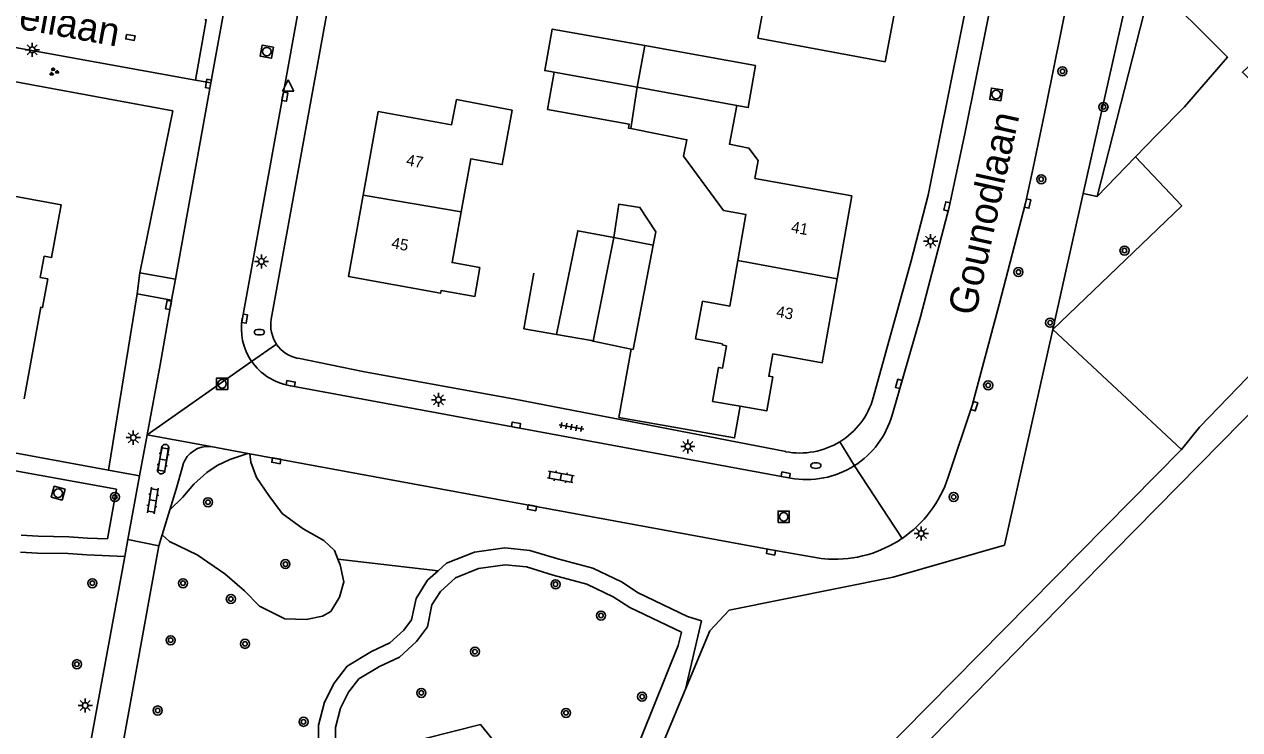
# Model space of a CAD drawing. Extents: x 132999 to 136000, y 398499 to 400501.
# Drawn here: x 133145.7 to 133253.2, y 398932.2 to 398994.6 of the extents above; entities that cross this region are included whole.
import ezdxf

# ---------------------------------------------------------------- set-up
doc = ezdxf.new("R2010")
doc.units = 0
for name, color, linetype in [('gg-afsc-erfafscheiding', 7, 'Continuous'), ('gg-afsc-hekwerk', 7, 'Continuous'), ('gg-afsc-muur', 7, 'Continuous'), ('gg-anno-huisnummerreeks BGT', 7, 'Continuous'), ('gg-anno-openbare ruimte label', 7, 'Continuous'), ('gg-bbg-bijgebouw', 7, 'Continuous'), ('gg-bbg-gedigitaliseerde bebouwing', 7, 'Continuous'), ('gg-bbg-gedigitaliseerde bijgebouw', 7, 'Continuous'), ('gg-bbg-hoofdgebouw', 7, 'Continuous'), ('gg-bbg-tussenscheiding', 7, 'Continuous'), ('gg-knt-verharding', 7, 'Continuous'), ('gt-grn-groengrens', 7, 'Continuous'), ('gt-grn-vlakafsluiter', 7, 'Continuous'), ('gt-grn-weggrens', 7, 'Continuous'), ('gt-symb-boom', 7, 'Continuous'), ('gt-symb-brandkraan', 7, 'Continuous'), ('gt-symb-groenvak', 7, 'Continuous'), ('gt-symb-klinker verharding', 7, 'Continuous'), ('gt-symb-kolk', 7, 'Continuous'), ('gt-symb-kolk center center', 7, 'Continuous'), ('gt-symb-lichtmast', 7, 'Continuous'), ('gt-symb-rioolschacht', 7, 'Continuous'), ('gt-symb-tegel verharding', 7, 'Continuous'), ('gt-symb-waterafsluiter', 7, 'Continuous')]:
    doc.layers.add(name, color=color, linetype=linetype)

# ---------------------------------------------------------------- blocks, each defined once
blk = doc.blocks.new('gt0-BOOM')
at = {"layer": 'gt-symb-boom'}
for radius in [0.4, 0.2]:
    blk.add_circle((0, 0), radius, dxfattribs=at)
blk = doc.blocks.new('gt0-LMAST')
at = {"layer": 'gt-symb-lichtmast'}
for p, q in [((-0.18, 0.17), (-0.45, 0.44)), ((-0.01, 0.25), (-0.01, 0.62)), ((0.17, 0.17), (0.44, 0.44)), ((-0.26, 0), (-0.63, 0)), ((-0.18, -0.18), (-0.45, -0.45)), ((-0.01, -0.25), (-0.01, -0.63)), ((0.44, -0.45), (0.17, -0.18)), ((0.24, 0), (0.62, 0))]:
    blk.add_line(p, q, dxfattribs=at)
blk.add_circle((-0.01, 0), 0.25, dxfattribs=at)
blk = doc.blocks.new('gt0-KOLK')
at = {"layer": 'gt-symb-kolk'}
blk.add_lwpolyline([(0, 0), (0.37, 0), (0.37, 0.4), (-0.38, 0.4), (-0.38, 0), (0, 0)], dxfattribs=at)
blk = doc.blocks.new('gt0-RS')
at = {"layer": 'gt-symb-rioolschacht'}
blk.add_lwpolyline([(-0.5, -0.5), (0.5, -0.5), (0.5, 0.5), (-0.5, 0.5)], close=True, dxfattribs=at)
blk.add_circle((0, 0), 0.375, dxfattribs=at)
blk = doc.blocks.new('gt0-BR')
at = {"layer": 'gt-symb-brandkraan'}
for centre, radius, start, end in [((-0.24, 0), 0.206, 107.5669, 252.4331), ((0.6, -2.66), 3, 106.892, 107.5669), ((0, -0.69), 0.938, 73.108, 106.892), ((-0.6, -2.66), 3, 72.4331, 73.108), ((0.24, 0), 0.206, 287.567, 72.4331), ((0.6, 2.66), 3, 252.4331, 253.108), ((0, 0.69), 0.938, 253.108, 286.8921), ((-0.6, 2.66), 3, 286.8921, 287.567)]:
    blk.add_arc(centre, radius, start, end, dxfattribs=at)
blk = doc.blocks.new('gt0-KOLKCC')
at = {"layer": 'gt-symb-kolk center center'}
blk.add_lwpolyline([(-0.38, 0.2), (0.38, 0.2), (0.38, -0.2), (-0.38, -0.2)], close=True, dxfattribs=at)
blk = doc.blocks.new('gt0-GRVAK')
at = {"layer": 'gt-symb-groenvak'}
for p, q in [((-0.11, 0.19), (-0.23, 0.24)), ((-0.18, 0.15), (0.09, 0.15)), ((-0.09, 0.21), (-0.16, 0.32)), ((-0.05, 0.21), (-0.05, 0.39)), ((0, 0.21), (0.06, 0.32)), ((0.01, 0.19), (0.13, 0.24)), ((0.26, -0.05), (0.2, 0.06)), ((0.3, -0.05), (0.3, 0.13)), ((0.35, -0.05), (0.41, 0.06)), ((-0.24, -0.23), (-0.36, -0.18)), ((-0.32, -0.26), (-0.05, -0.26)), ((-0.23, -0.21), (-0.29, -0.09)), ((-0.18, -0.2), (-0.18, -0.02)), ((-0.14, -0.21), (-0.07, -0.09)), ((-0.12, -0.23), (0, -0.18)), ((0.24, -0.07), (0.12, -0.02)), ((0.17, -0.11), (0.44, -0.11)), ((0.37, -0.07), (0.49, -0.02))]:
    blk.add_line(p, q, dxfattribs=at)
blk = doc.blocks.new('gt0-WAFSL')
at = {"layer": 'gt-symb-waterafsluiter'}
for p, q in [((-0.5, -0.33), (0, 0.67)), ((0, 0.67), (0.5, -0.33)), ((0.5, -0.33), (-0.5, -0.33))]:
    blk.add_line(p, q, dxfattribs=at)
blk = doc.blocks.new('gt0-TEG1')
at = {"layer": 'gt-symb-tegel verharding'}
for p, q in [((-1.12, 0), (1.12, 0)), ((-0.9, -0.25), (-0.9, 0.25)), ((-0.45, -0.25), (-0.45, 0.25)), ((0, -0.25), (0, 0.25)), ((0.45, -0.25), (0.45, 0.25)), ((0.9, -0.25), (0.9, 0.25))]:
    blk.add_line(p, q, dxfattribs=at)
blk = doc.blocks.new('gt0-KL1')
at = {"layer": 'gt-symb-klinker verharding'}
for p, q in [((-1.15, 0.3), (1.15, 0.3)), ((-1, -0.3), (-1, 0.3)), ((-0.5, 0.3), (-0.5, 0.45)), ((0, -0.3), (0, 0.3)), ((0.5, 0.3), (0.5, 0.45)), ((1, -0.3), (1, 0.3)), ((-1.15, -0.3), (1.15, -0.3)), ((-0.5, -0.45), (-0.5, -0.3)), ((0.5, -0.45), (0.5, -0.3))]:
    blk.add_line(p, q, dxfattribs=at)

msp = doc.modelspace()

# ---------------------------------------------------------------- linework, layer by layer
at = {"layer": 'gg-afsc-erfafscheiding'}
msp.add_line((133236.7, 398967.6), (133239.4, 398979.64), dxfattribs=at)
for points in [[(133239.4, 398979.64), (133244.97, 399004.49), (133252.84, 399038.49)], [(133208.08, 398942.76), (133222.58, 398945.69), (133232.42, 398948.53), (133236.7, 398967.6)]]:
    msp.add_lwpolyline(points, dxfattribs=at)
at = {"layer": 'gg-afsc-hekwerk'}
for points in [[(133208.08, 398942.76), (133206.38, 398940.95), (133204.22, 398935.79)], [(133204.22, 398935.79), (133193.8, 398910.84), (133190.05, 398872.02)]]:
    msp.add_lwpolyline(points, dxfattribs=at)
at = {"layer": 'gg-afsc-muur'}
msp.add_line((133189.13, 398961.44), (133175.67, 398963.87), dxfattribs=at)
for points in [[(133192.82, 398967.15), (133189.93, 398967.66), (133190.8, 398972.58)], [(133199.41, 398965.87), (133198.32, 398959.82), (133208.56, 398958), (133209.06, 398960.81)]]:
    msp.add_lwpolyline(points, dxfattribs=at)
at = {"layer": 'gg-bbg-bijgebouw'}
for p, q in [((133196.04, 398966.58), (133199.41, 398965.87)), ((133199.41, 398965.87), (133199.6, 398965.84))]:
    msp.add_line(p, q, dxfattribs=at)
for points in [[(133208.77, 398987.41), (133209.76, 398987.23), (133210.42, 398990.96)], [(133192.82, 398967.15), (133195.9, 398966.61), (133196.04, 398966.58)]]:
    msp.add_lwpolyline(points, dxfattribs=at)
at = {"layer": 'gg-bbg-gedigitaliseerde bebouwing'}
msp.add_line((133210.6, 398993.37), (133212.1, 399001.43), dxfattribs=at)
for points in [[(133184.38, 398978.01), (133185.22, 398982.69), (133188, 398982.19), (133188.87, 398986.99), (133183.96, 398987.94)], [(133199.37, 398985.37), (133204.34, 398984.39), (133204.05, 398982.94), (133207.58, 398978.13)], [(133186.03, 398973.07), (133183.57, 398973.52), (133184.38, 398978.01)], [(133208.85, 398973.71), (133209.56, 398977.78), (133207.58, 398978.13)], [(133205.71, 398970.1), (133208.14, 398969.67), (133208.85, 398973.71)]]:
    msp.add_lwpolyline(points, dxfattribs=at)
at = {"layer": 'gg-bbg-gedigitaliseerde bijgebouw'}
for p, q in [((133210.42, 398990.96), (133200.61, 398992.71)), ((133199.6, 398965.84), (133201.37, 398975.06))]:
    msp.add_line(p, q, dxfattribs=at)
for points in [[(133200.61, 398992.71), (133192.43, 398994.17), (133191.77, 398990.5), (133192.59, 398990.35)], [(133192.59, 398990.35), (133192.01, 398987.07), (133199.23, 398985.77), (133199.16, 398985.41), (133199.37, 398985.37)], [(133197.87, 398975.74), (133198.33, 398978.69), (133200.18, 398978.4), (133201.59, 398976.23), (133201.37, 398975.06)], [(133192.82, 398967.15), (133194.68, 398976.34), (133197.87, 398975.74)]]:
    msp.add_lwpolyline(points, dxfattribs=at)
at = {"layer": 'gg-bbg-hoofdgebouw'}
for p, q in [((133221.88, 398991.28), (133223.42, 398999.37)), ((133210.6, 398993.37), (133221.88, 398991.28)), ((133218.94, 398979.41), (133217.63, 398972.08))]:
    msp.add_line(p, q, dxfattribs=at)
for points in [[(133183.96, 398987.94), (133183.53, 398985.71), (133177.04, 398986.87), (133175.71, 398979.47)], [(133218.94, 398979.41), (133210.35, 398980.97), (133210.63, 398982.55), (133209.83, 398983.65), (133208.1, 398983.99), (133208.77, 398987.41)], [(133127.48, 398979.52), (133134.85, 398978.18), (133135.41, 398981.11), (133141.33, 398980.04), (133141.44, 398980.64), (133142.83, 398980.39), (133142.72, 398979.79), (133149, 398978.62), (133148.15, 398973.96), (133147.49, 398974.08), (133147.14, 398972.19), (133147.8, 398972.07), (133147.35, 398969.54), (133147.19, 398969.57), (133145.72, 398961.45)], [(133175.71, 398979.47), (133174.42, 398972.28), (133182.55, 398970.81), (133182.59, 398971.04), (133185.59, 398970.52), (133186.03, 398973.07)], [(133217.63, 398972.08), (133216.32, 398964.66), (133211.93, 398965.44)], [(133205.71, 398970.1), (133205.11, 398966.76), (133207.48, 398966.34), (133207.46, 398966.23), (133207.85, 398966.16)], [(133207.85, 398966.16), (133207.5, 398964.18), (133207.15, 398964.24), (133206.61, 398961.24), (133209.06, 398960.81)], [(133209.06, 398960.81), (133211.4, 398960.39), (133211.93, 398963.4), (133211.58, 398963.46), (133211.93, 398965.44)]]:
    msp.add_lwpolyline(points, dxfattribs=at)
at = {"layer": 'gg-bbg-tussenscheiding'}
for p, q in [((133199.95, 398989.03), (133200.61, 398992.71)), ((133199.95, 398989.03), (133192.59, 398990.35)), ((133199.95, 398989.03), (133199.37, 398985.37)), ((133199.95, 398989.03), (133208.77, 398987.41)), ((133175.71, 398979.47), (133184.38, 398978.01)), ((133196.04, 398966.58), (133197.87, 398975.74)), ((133197.87, 398975.74), (133201.37, 398975.06)), ((133208.85, 398973.71), (133217.63, 398972.08))]:
    msp.add_line(p, q, dxfattribs=at)
at = {"layer": 'gg-knt-verharding'}
for p, q in [((133185.23, 399065.78), (133167.57, 398968.5)), ((133162.23, 398989.41), (133169.19, 399028.01)), ((133165.02, 398968.61), (133175.6, 399026.92)), ((133136.32, 398994.11), (133160.87, 398989.66)), ((133160.87, 398989.66), (133162.23, 398989.41)), ((133162.23, 398989.41), (133159.1, 398972.04)), ((133155.95, 398972.61), (133159.1, 398972.04)), ((133159.1, 398972.04), (133158.76, 398970.19)), ((133155.71, 398970.74), (133158.76, 398970.19)), ((133169.94, 398965.05), (133175.67, 398963.87)), ((133169.13, 398962.64), (133213.5, 398954.45)), ((133189.13, 398961.44), (133213.08, 398956.79)), ((133156.59, 398958.27), (133155.92, 398954.64)), ((133157.91, 398957.19), (133157.53, 398955.25)), ((133158.17, 398955.12), (133158.5, 398957.08)), ((133162.23, 398957.24), (133165.51, 398956.64)), ((133165.51, 398956.64), (133165.68, 398956.61)), ((133155.92, 398954.64), (133154.89, 398949.03)), ((133157.91, 398949.42), (133158.59, 398951.65)), ((133154.89, 398949.03), (133154.61, 398947.52)), ((133154.89, 398949.03), (133157.62, 398948.47)), ((133157.62, 398948.47), (133157.91, 398949.42)), ((133157.62, 398948.47), (133146.42, 398886.21)), ((133154.61, 398947.52), (133143.5, 398887.15))]:
    msp.add_line(p, q, dxfattribs=at)
for points in [[(133245.65, 399088.76), (133237.06, 399036.07), (133225.68, 398979.49), (133224.19, 398973.68), (133220.82, 398961.55)], [(133236.73, 399023.76), (133228.96, 398985.05), (133227.54, 398978.41), (133224.99, 398968.72), (133222.49, 398960.02)], [(133227.46, 398954.52), (133229.57, 398960.86), (133231.97, 398969.81), (133234.29, 398978.78), (133234.98, 398981.91), (133236.16, 398987.56), (133238.65, 399000)], [(133160.87, 398989.66), (133161.82, 398995), (133161.7, 398995.02)], [(133156.59, 398958.27), (133157.74, 398964.48), (133158.76, 398970.19)], [(133165.68, 398956.61), (133211.81, 398948.11), (133216.22, 398947.33), (133216.87, 398947.28)], [(133158.59, 398951.65), (133159.15, 398953.48), (133159.77, 398955.65)]]:
    msp.add_lwpolyline(points, dxfattribs=at)
for centre, radius, start, end in [((133170.06, 398967.69), 5.13, 169.6962, 214.6036), ((133170.5, 398967.97), 2.97, 169.7471, 214.4424), ((133170.5, 398967.97), 2.98, 214.4496, 259.1396), ((133170.07, 398967.69), 5.13, 214.6002, 259.5114), ((133214.34, 398963.42), 6.75, 301.5898, 343.9704), ((133214.93, 398962.19), 7.87, 302.4926, 343.965), ((133158.21, 398957.14), 0.299, 348.827, 170.5461), ((133214.34, 398963.42), 6.75, 259.2105, 301.5757), ((133162.02, 398954.87), 2.39, 85.0351, 160.9701), ((133157.84, 398955.16), 0.329, 164.4779, 353.5531), ((133214.93, 398962.19), 7.87, 259.5517, 302.5107), ((133217.39, 398957.88), 10.61, 304.3647, 341.5569), ((133217.39, 398957.88), 10.61, 267.1793, 304.3791)]:
    msp.add_arc(centre, radius, start, end, dxfattribs=at)
at = {"layer": 'gt-grn-groengrens'}
for p, q in [((133245.47, 398998.38), (133240.62, 398979.37)), ((133240.62, 398979.37), (133244.02, 398982.88)), ((133240.62, 398979.37), (133239.4, 398979.64)), ((133155.71, 398970.74), (133153.18, 398955.15)), ((133236.7, 398967.6), (133248.08, 398956.98)), ((133248.08, 398956.98), (133215.49, 398923.97)), ((133182.33, 398946.26), (133173.47, 398947.28))]:
    msp.add_line(p, q, dxfattribs=at)
for points in [[(133248.08, 398956.98), (133249.67, 398958.97), (133266.46, 398976.33), (133266.18, 398977.71), (133253.48, 398990.35), (133255.07, 398991.83), (133267.74, 398978.85), (133269.14, 398978.85), (133288.75, 398998.82), (133288.52, 399001.06), (133260.35, 399028.51)], [(133244.02, 398982.88), (133245.88, 398984.8), (133248.37, 398987.31), (133252.17, 398991.68), (133245.47, 398998.38)], [(133135.85, 398991.18), (133158.86, 398986.93), (133155.95, 398972.61)], [(133244.02, 398982.88), (133248.11, 398978.53), (133236.7, 398967.6)], [(133216.92, 398922.56), (133224.88, 398930.31), (133242.11, 398947.97), (133259.16, 398965.28), (133259.65, 398965.28), (133279.59, 398945.51)], [(133095.38, 398964.05), (133153.88, 398953.46), (133153.08, 398949.08), (133151.33, 398949.15), (133149.68, 398949.27), (133146.95, 398949.3), (133145.46, 398949.4)], [(133165.51, 398956.64), (133163.91, 398956.11), (133162.8, 398955.56), (133161.88, 398954.95), (133160.74, 398953.9), (133159.71, 398952.74), (133158.59, 398951.65)], [(133173.47, 398947.28), (133173.17, 398948.05), (133172.23, 398948.93), (133170.41, 398949.97), (133168.54, 398951.32), (133167.35, 398952.91), (133166.28, 398954.5), (133165.78, 398955.85), (133165.68, 398956.61)], [(133173.47, 398947.28), (133173.67, 398946.78), (133173.98, 398945.27), (133173.6, 398943.92), (133172.85, 398942.65), (133172.1, 398942.25), (133170.66, 398941.93), (133168.78, 398942.01), (133166.53, 398943.12), (133165.22, 398944.48), (133163.46, 398945.99), (133161.02, 398947.66), (133158.58, 398948.85), (133157.91, 398949.42)], [(133154.61, 398947.52), (133151.25, 398947.65), (133149.62, 398947.77), (133146.89, 398947.81), (133145.4, 398947.9)], [(133204.22, 398935.79), (133205.62, 398941.81), (133204.4, 398942.22), (133200.03, 398944.3), (133198.55, 398945.26), (133196.01, 398946.47), (133192.93, 398947.3), (133190.46, 398948.06), (133188.23, 398948.29), (133185.54, 398947.91), (133183.07, 398946.93), (133182.33, 398946.26)], [(133173.25, 398931.26), (133173.25, 398932.39), (133173.7, 398934.09), (133174.41, 398935.5), (133175.31, 398936.68), (133177.15, 398937.78), (133178.91, 398938.61), (133180.41, 398939.99), (133181.39, 398941.28), (133181.79, 398943.25), (133182.54, 398944.43), (133183.88, 398945.63), (133185.92, 398946.45), (133188.26, 398946.78), (133190.16, 398946.59), (133192.51, 398945.86), (133195.48, 398945.06), (133197.82, 398943.94), (133199.3, 398942.99), (133203.85, 398940.82), (133203.58, 398939.65), (133191.98, 398910.84)], [(133171.75, 398931.14), (133171.75, 398932.58), (133172.29, 398934.63), (133173.14, 398936.3), (133174.29, 398937.82), (133176.45, 398939.11), (133178.07, 398939.87), (133179.3, 398941.01), (133179.99, 398941.92), (133180.38, 398943.81), (133181.38, 398945.41), (133182.33, 398946.26)], [(133187.92, 398930.38), (133186.07, 398932.64), (133181.19, 398931.4)]]:
    msp.add_lwpolyline(points, dxfattribs=at)
at = {"layer": 'gt-grn-vlakafsluiter'}
for p, q in [((133155.95, 398972.61), (133155.71, 398970.74)), ((133144.86, 398956.68), (133153.18, 398955.15)), ((133153.18, 398955.15), (133155.92, 398954.64))]:
    msp.add_line(p, q, dxfattribs=at)
at = {"layer": 'gt-grn-weggrens'}
for p, q in [((133165.84, 398964.78), (133168.05, 398966.29)), ((133156.59, 398958.27), (133165.84, 398964.78)), ((133156.59, 398958.27), (133162.23, 398957.24)), ((133217.87, 398957.67), (133219.16, 398955.55)), ((133219.16, 398955.55), (133223.38, 398949.12))]:
    msp.add_line(p, q, dxfattribs=at)

# ---------------------------------------------------------------- block references
at = {"layer": 'gt-symb-boom'}
for p in [(133237.56, 398990.44), (133241.19, 398987.29), (133235.68, 398980.89), (133243.05, 398974.58), (133233.67, 398972.68), (133236.47, 398968.2), (133230.99, 398962.66), (133153.74, 398952.78), (133227.94, 398952.78), (133161.98, 398952.32), (133168.83, 398946.84), (133151.75, 398945.15), (133159.77, 398945.15), (133192.72, 398945.06), (133164, 398943.76), (133196.74, 398942.29), (133158.67, 398940.11), (133165.25, 398939.79), (133185.59, 398939.1), (133150.38, 398937.99), (133180.85, 398935.45), (133200.38, 398935.11), (133157.53, 398933.89), (133193.64, 398933.68), (133170.43, 398932.89)]:
    msp.add_blockref('gt0-BOOM', p, dxfattribs=at)
at = {"layer": 'gt-symb-brandkraan'}
for p in [(133166.52, 398967.36), (133215.74, 398955.56)]:
    msp.add_blockref('gt0-BR', p, dxfattribs=at)
at = {"layer": 'gt-symb-groenvak'}
msp.add_blockref('gt0-GRVAK', (133148.33, 398990.4), dxfattribs=at)
at = {"layer": 'gt-symb-klinker verharding'}
for p, rotation in [((133158.01, 398956.09), -99.09480497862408), ((133193.18, 398954.56), -10.422654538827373), ((133157.1, 398952.48), -99.02919884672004)]:
    msp.add_blockref('gt0-KL1', p, dxfattribs=dict(at, rotation=rotation))
at = {"layer": 'gt-symb-kolk'}
for p, rotation in [((133162.21, 398989.3), 79.77744077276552), ((133168.58, 398988.23), -100.19720557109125), ((133227.54, 398978.45), 76.7004156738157), ((133234.29, 398978.78), -102.827123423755), ((133158.68, 398969.73), 79.63367739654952), ((133165.02, 398968.58), -98.97262661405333), ((133169.26, 398962.62), -10.950434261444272), ((133223.27, 398962.73), 74.0309834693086), ((133229.57, 398960.86), -106.62239613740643), ((133189.19, 398958.94), -10.366322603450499), ((133168.05, 398956.18), 169.69002960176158), ((133213.04, 398954.53), -10.42265453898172), ((133190.67, 398952.02), 169.57734546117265), ((133211.81, 398948.11), 169.5669752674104)]:
    msp.add_blockref('gt0-KOLK', p, dxfattribs=dict(at, rotation=rotation))
at = {"layer": 'gt-symb-kolk center center', "rotation": -10.295463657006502}
msp.add_blockref('gt0-KOLKCC', (133155.12, 398993.44), dxfattribs=at)
at = {"layer": 'gt-symb-lichtmast'}
for p in [(133146.44, 398992.34), (133225.91, 398975.41), (133166.71, 398973.62), (133182.37, 398961.38), (133155.38, 398958.03), (133204.43, 398957.25), (133225.08, 398949.55), (133151.13, 398934.33)]:
    msp.add_blockref('gt0-LMAST', p, dxfattribs=at)
at = {"layer": 'gt-symb-rioolschacht'}
for p, rotation in [((133167.18, 398992.18), 169.80279442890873), ((133231.7, 398988.39), 81.2538377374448), ((133148.73, 398953.12), 164.44827510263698)]:
    msp.add_blockref('gt0-RS', p, dxfattribs=dict(at, rotation=rotation))
for p in [(133163.22, 398962.79), (133212.9, 398951.03)]:
    msp.add_blockref('gt0-RS', p, dxfattribs=at)
at = {"layer": 'gt-symb-tegel verharding', "rotation": -10.489389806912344}
msp.add_blockref('gt0-TEG1', (133194.13, 398958.97), dxfattribs=at)
at = {"layer": 'gt-symb-waterafsluiter'}
msp.add_blockref('gt0-WAFSL', (133169.07, 398989.01), dxfattribs=at)

# ---------------------------------------------------------------- texts
at = {"layer": 'gg-anno-huisnummerreeks BGT'}
for s, rotation, p in [('47', 349.8, (133179.46, 398982.13)), ('41', 349.9, (133213.51, 398976.2)), ('45', 349.8, (133178.15, 398974.8)), ('43', 350.1, (133212.19, 398968.72))]:
    msp.add_text(s, height=1, rotation=rotation, dxfattribs=at).set_placement(p)
at = {"layer": 'gg-anno-openbare ruimte label'}
for s, rotation, p in [('Ravellaan', 349.7, (133139.29, 398995.28)), ('Gounodlaan', 77.6, (133229.85, 398968.72))]:
    msp.add_text(s, height=2.5, rotation=rotation, dxfattribs=at).set_placement(p)

doc.saveas('drawing.dxf')
